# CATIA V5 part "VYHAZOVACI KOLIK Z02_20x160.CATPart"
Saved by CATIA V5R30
Part number: VYHAZOVACI KOLIK Z02/20x160
Bounding box of the stored display mesh (mm): x -160 to 0, y -10 to 10, z -10 to 10
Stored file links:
  C:\Users\ondra\Desktop\PŘÍLOHA P III\CATIA\VYHAZOVACI KOLIK Z02_20x160.CATPart
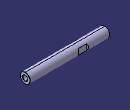
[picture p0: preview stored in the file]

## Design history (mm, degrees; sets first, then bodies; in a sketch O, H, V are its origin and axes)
Set1
  DatumSurface1 to DatumSurface26 "Z02/20x1"
  Join1: Elements (DatumSurface1; DatumSurface2; DatumSurface3; DatumSurface4; DatumSurface5; DatumSurface6; DatumSurface7; DatumSurface8; DatumSurface9; DatumSurface10; DatumSurface11; DatumSurface12; DatumSurface13; DatumSurface14; DatumSurface15; DatumSurface16; DatumSurface17; DatumSurface18; DatumSurface19; DatumSurface20; DatumSurface21; DatumSurface22; DatumSurface23; DatumSurface24; DatumSurface25; DatumSurface26)
Body1 (main body)
  CloseSurface1: CloseElement Join1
